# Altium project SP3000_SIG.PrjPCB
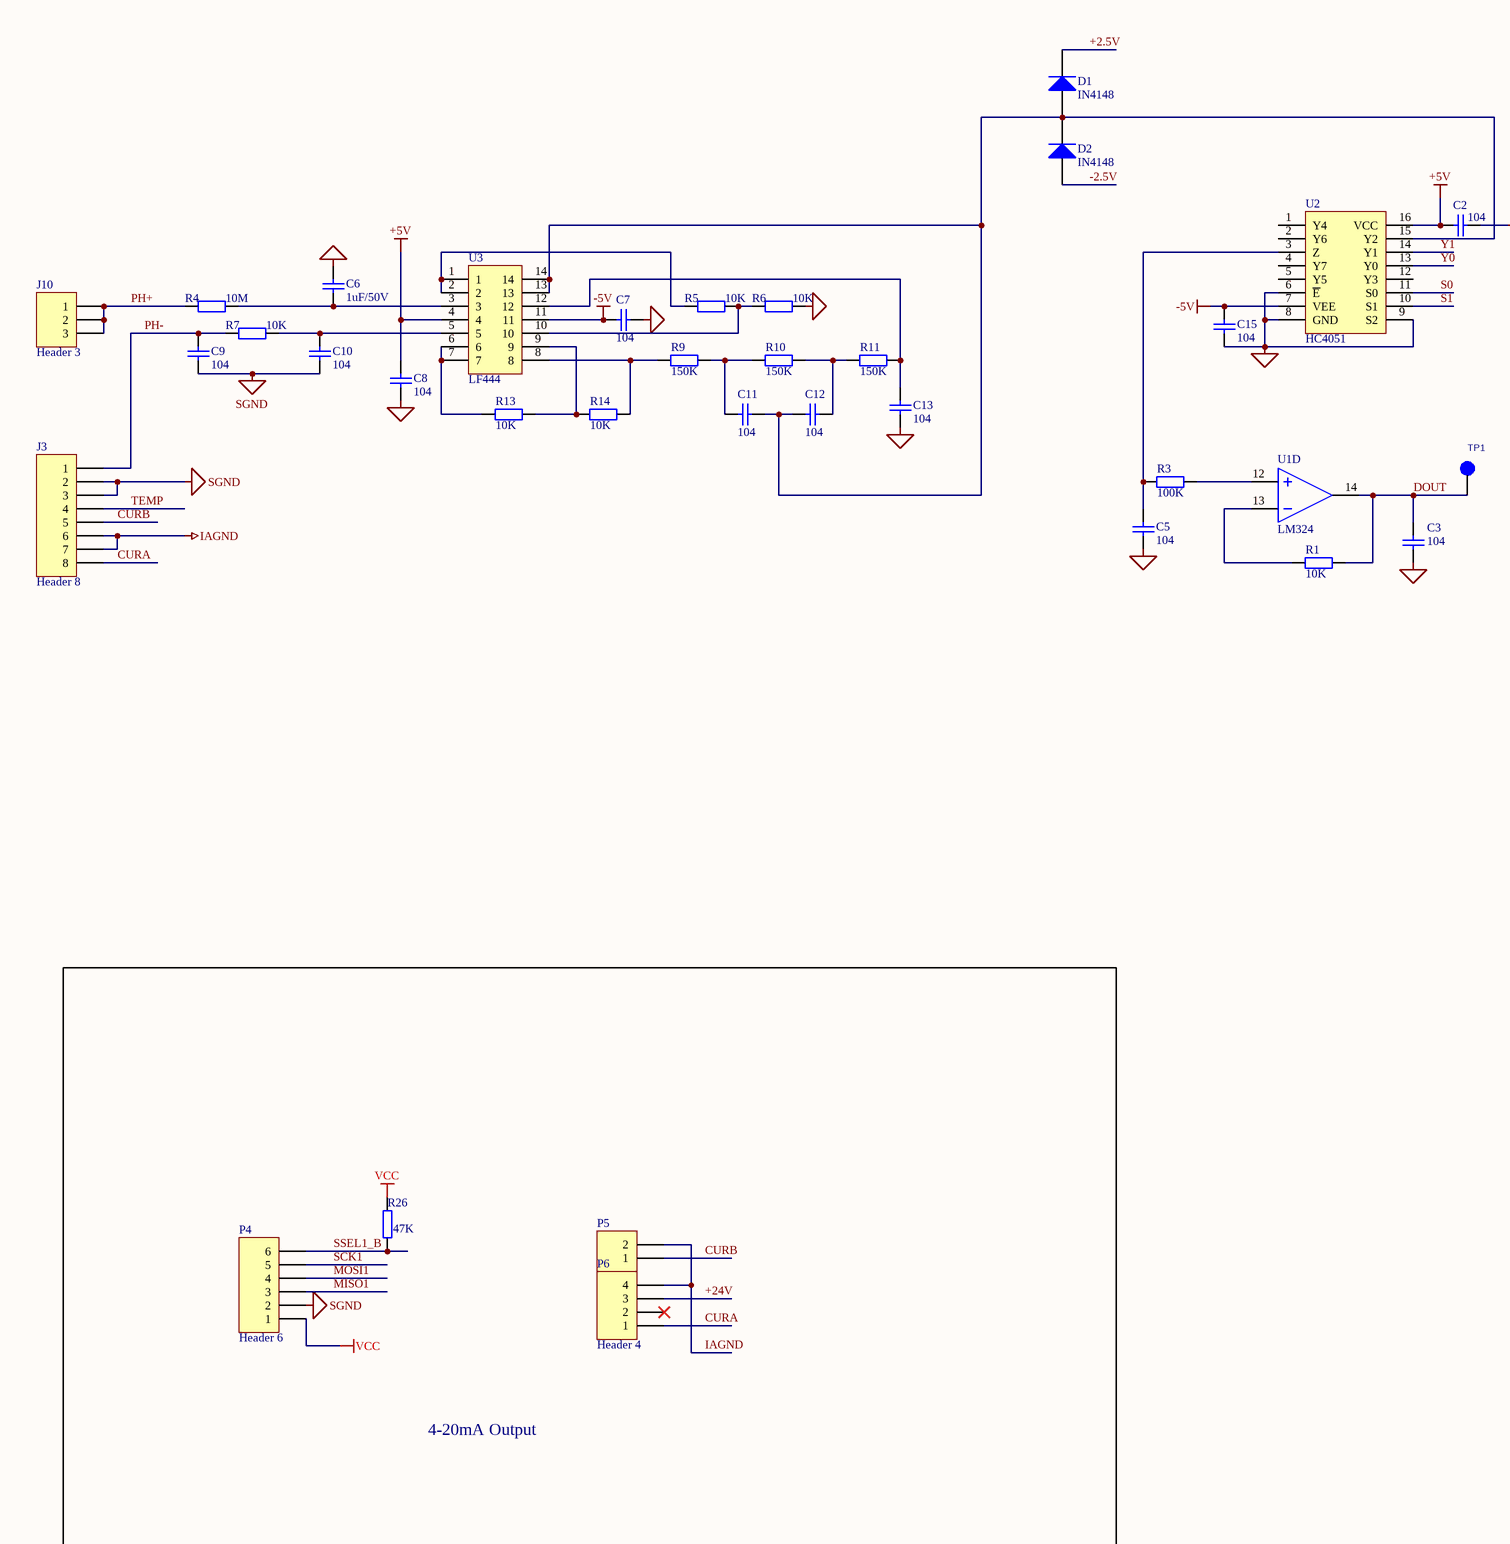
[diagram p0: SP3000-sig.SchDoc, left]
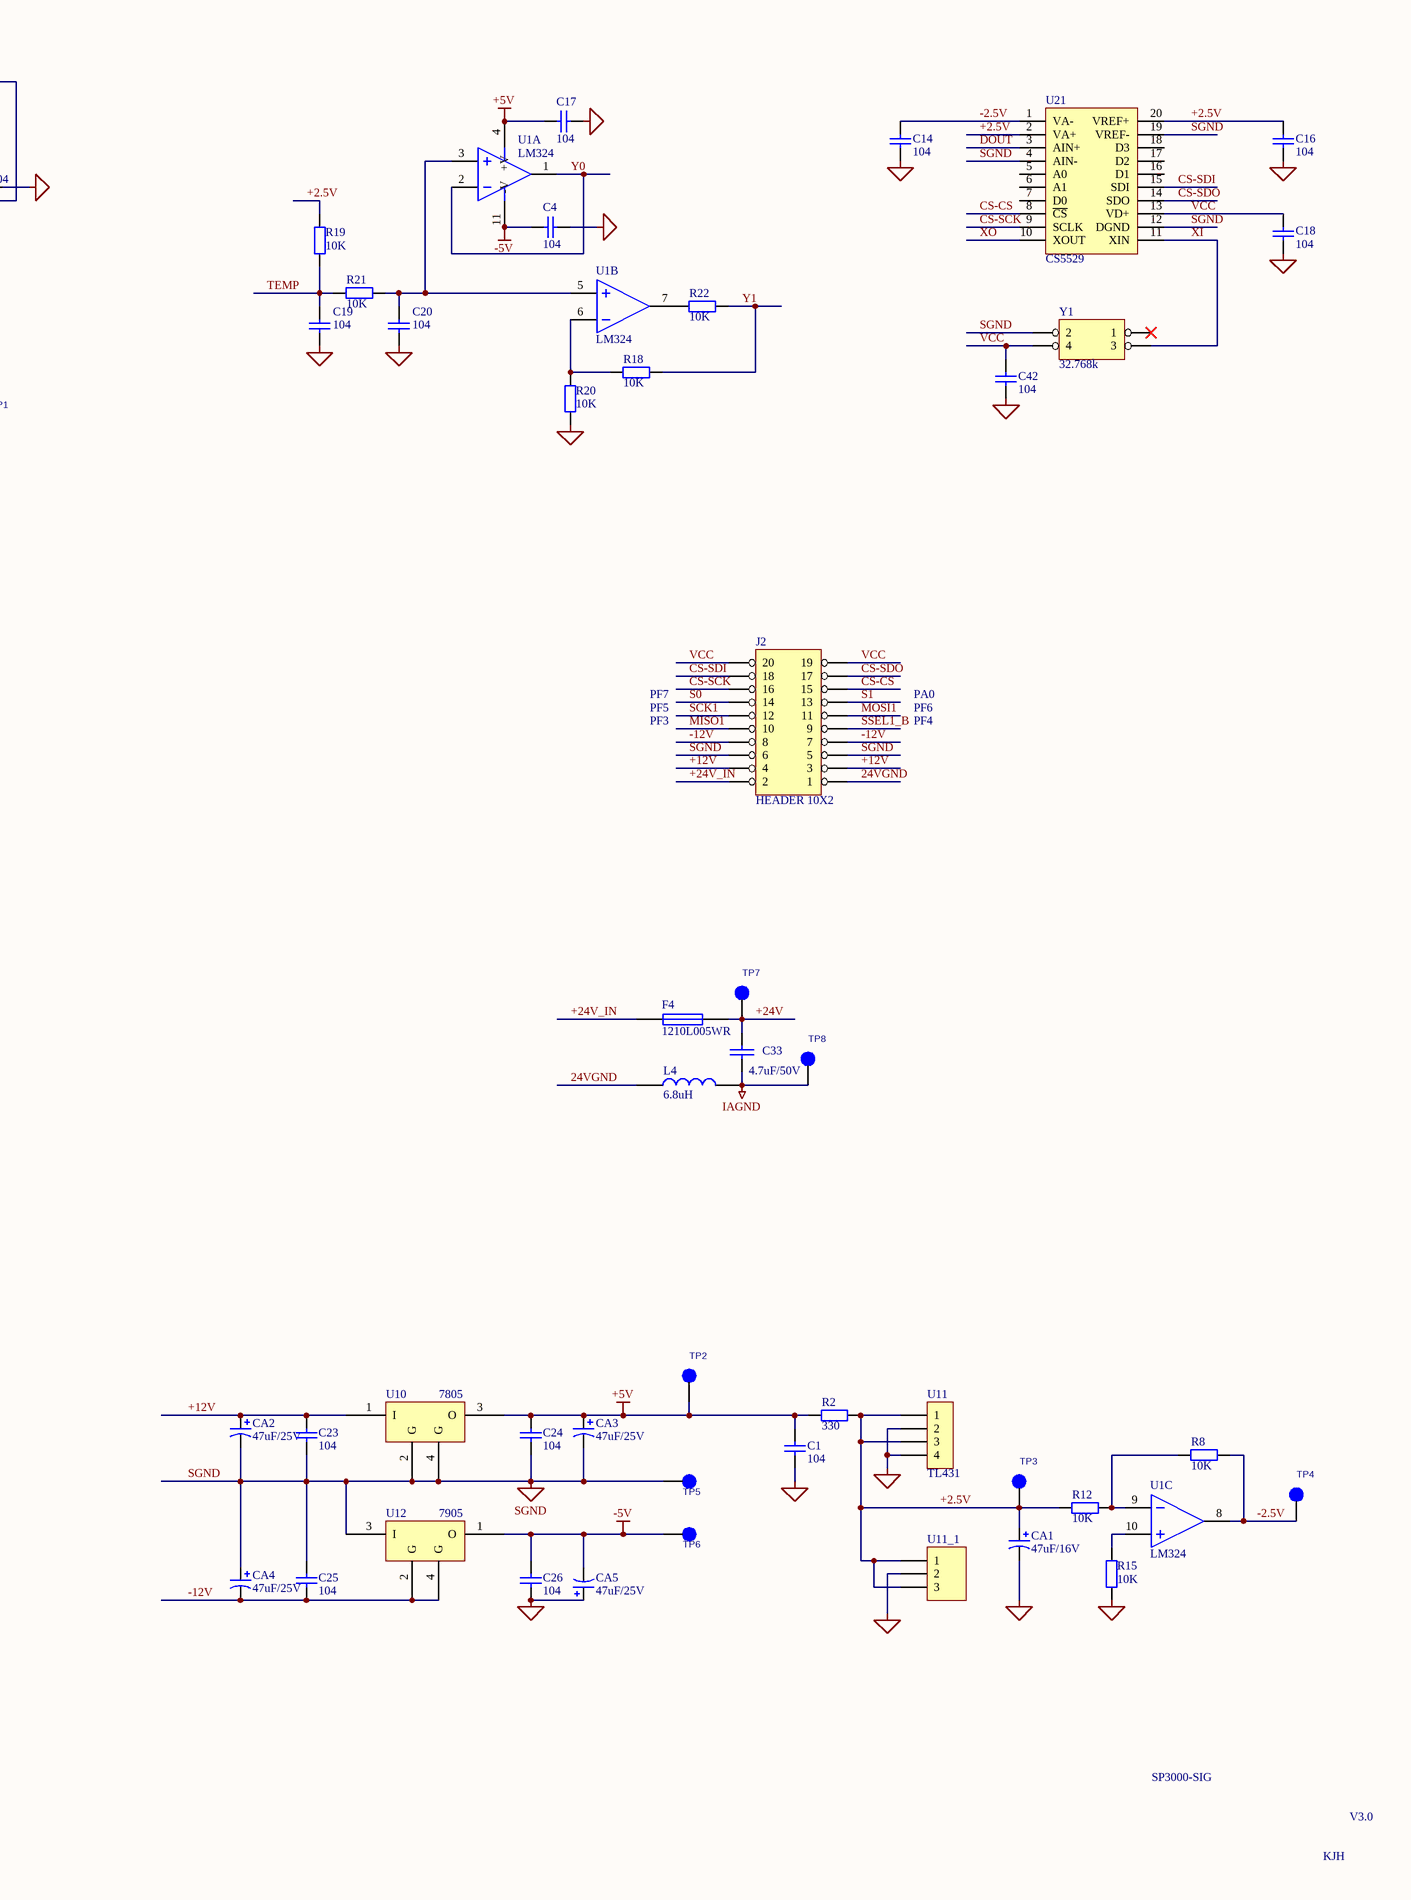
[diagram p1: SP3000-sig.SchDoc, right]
1 sheet, 79 parts. Net scope: global (net labels, ports and power ports of the same name join across sheets).
Board file: SP3000_SIG_V5.2.PcbDoc

## Sheet SP3000-sig.SchDoc
size A2; SheetNumber: 0; SheetTotal: 0

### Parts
C1  104  [0603]
C2  104  [0603]
C3  104  [0603]
C4  104  [0603]
C5  104  [0603]
C6  1uF/50V  [1808C]
C7  104  [0603]
C8  104  [0603]
C9  104  [0603]
C10  104  [0603]
C11  104  [0603]
C12  104  [0603]
C13  104  [0603]
C14  104  [0603]
C15  104  [0603]
C16  104  [0603]
C17  104  [0603]
C18  104  [0603]
C19  104  [0603]
C20  104  [0603]
C23  104  [0603]
C24  104  [0603]
C25  104  [0603]
C26  104  [0603]
C33  4.7uF/50V  [1206]
C42  104  [0603]
CA1  47uF/16V  [1206C]
CA2  47uF/25V  [1206C]
CA3  47uF/25V  [1206C]
CA4  47uF/25V  [1206C]
CA5  47uF/25V  [1206C]
D1  IN4148  [1206]
D2  IN4148  [1206]
F4  1210L005WR  [1206]
J2  HEADER 10X2  [IDC20]
J3  Header 8  [W2318R5MIL]
J10  Header 3  [W2313R5MIL]
L4  6.8uH  [LPS3010]
P4  Header 6  [HDR1X6]
P5  Header 2  [HDR1X2]  (value not drawn)
P6  Header 4  [HDR1X4]
R1  10K  [0603]
R2  330  [0603]
R3  100K  [0603]
R4  10M  [0603]
R5  10K  [0603]
R6  10K  [0603]
R7  10K  [0603]
R8  10K  [0603]
R9  150K  [0603]
R10  150K  [0603]
R11  150K  [0603]
R12  10K  [0603]
R13  10K  [0603]
R14  10K  [0603]
R15  10K  [0603]
R18  10K  [0603]
R19  10K  [0603]
R20  10K  [0603]
R21  10K  [0603]
R22  10K  [0603]
R26  47K  [0603A]
TP1  DOUT  [test point]  (value not drawn)
TP2  P5V  [test point]  (value not drawn)
TP3  P2.5V  [test point]  (value not drawn)
TP4  N2.5V  [test point]  (value not drawn)
TP5  GND  [test point]  (value not drawn)
TP6  N5V  [test point]  (value not drawn)
TP7  P24V  [test point]  (value not drawn)
TP8  AGND  [test point]  (value not drawn)
U1  LM324  [SOP14]  (parts A,B,C,D of 4)
U2  HC4051  [SOP16MAX232]
U3  LF444  [SOP14]
U10  7805  [7805 - DUPLICATE]
U11  TL431  [7805 - DUPLICATE]
U11_1  TL431  [HDR1X3]  (value not drawn)
U12  7905
U21  CS5529  [CS5529]
Y1  32.768k  [CYU-SMD]

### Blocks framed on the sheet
4-20mA Output: P4-P6 R26

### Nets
+5V: C1.1 C2.2 C8.1 C17.1 C24.2 CA3.1 R2.2 TP2.1 U1.4(+V) U2.16(VCC) U3.4 U10.3(O)
-5V: C4.1 C7.1 C15.2 C26.2 CA5.2 TP6.1 U1.11(-V) U2.7(VEE) U3.11 U12.1(O)
IAGND: C33.2 J3.6 J3.7 L4.2 P5.2 P6.4 TP8.1
SGND: C1.2 C2.1 C3.1 C4.2 C5.2 C6.2 C7.2 C8.2 C9.1 C10.1 C13.2 C14.2 C15.1 C16.2 C17.2 C18.2 C19.1 C20.1 C23.1 C24.1 C25.2 C26.1 C42.2 CA1.2 CA2.2 CA3.2 CA4.1 CA5.1 J2.5 J2.6 J3.2 J3.3 P4.2 R6.2 R15.2 R20.2 TP5.1 U2.6(~{E}) U2.8(GND) U2.9(S2) U10.2(G) U10.4(G) U11.2 U11.4 U11_1.2 U12.3(I) U21.4(AIN-) U21.12(DGND) U21.19(VREF-) Y1.2
VCC: C18.1 C42.1 J2.19 J2.20 P4.1 R26.2 U21.13(VD+) Y1.4
24VGND: J2.1 L4.1
+2.5V: C16.1 CA1.1 D1.2(K) R2.1 R12.1 R19.1 TP3.1 U11.1 U11.3 U11_1.1 U11_1.3 U21.2(VA+) U21.20(VREF+)
+12V: C23.2 CA2.1 J2.3 J2.4 U10.1(I)
+24V: C33.1 F4.2 P6.3 TP7.1
+24V_IN: F4.1 J2.2
-2.5V: C14.1 D2.1(A) R8.2 TP4.1 U1.8(OUT) U21.1(VA-)
-12V: C25.1 CA4.2 J2.7 J2.8 U12.2(G) U12.4(G)
CS-CS: J2.15 U21.8(~{CS})
CS-SCK: J2.16 U21.9(SCLK)
CS-SDI: J2.18 U21.15(SDI)
CS-SDO: J2.17 U21.14(SDO)
CURA: J3.8 P6.1
CURB: J3.5 P5.1
DOUT: C3.2 R1.1 TP1.1 U1.14(OUT) U21.3(AIN+)
MISO1: J2.10 P4.3
MOSI1: J2.11 P4.4
PH+: J10.1 J10.2 J10.3 R4.1
PH-: C9.2 J3.1 R7.1
S0: J2.14 U2.11(S0)
S1: J2.13 U2.10(S1)
SCK1: J2.12 P4.5
SSEL1_B: J2.9 P4.6 R26.1
TEMP: C19.2 J3.4 R19.2 R21.2
XI: U21.11(XIN) Y1.3
XO: U21.10(XOUT)
Y0: U1.1(OUT) U1.2(IN-) U2.13(Y0)
Y1: R18.1 R22.1 U2.14(Y1)
NetC5_1: C5.1 R3.2 U2.3(Z)
NetC6_1: C6.1 R4.2 U3.3
NetC10_2: C10.2 R7.2 U3.5
NetC11_1: C11.1 R9.2 R10.1
NetC11_2: C11.2 C12.1 D1.1(A) D2.2(K) U2.15(Y2) U3.13 U3.14
NetC12_2: C12.2 R10.2 R11.1
NetC13_1: C13.1 R11.2 U3.12
NetC20_2: C20.2 R21.1 U1.3(IN+) U1.5(IN+)
NetR1_2: R1.2 U1.13(IN-)
NetR3_1: R3.1 U1.12(IN+)
NetR5_1: R5.1 U3.1 U3.2
NetR5_2: R5.2 R6.1 U3.10
NetR8_1: R8.1 R12.2 U1.9(IN-)
NetR9_1: R9.1 R14.2 U3.8
NetR13_1: R13.1 U3.6 U3.7
NetR13_2: R13.2 R14.1 U3.9
NetR15_1: R15.1 U1.10(IN+)
NetR18_2: R18.2 R20.1 U1.6(IN-)
NetR22_2: R22.2 U1.7(OUT)

Not connected (* = marked no-connect by the designer): P6 2*; U2 1(Y4) 2(Y6) 4(Y7) 5(Y5) 12(Y3); U21 5(A0) 6(A1) 7(D0) 16(D1) 17(D2) 18(D3); Y1 1*

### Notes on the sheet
- PF3
- PF5
- PF7
- PF4
- PF6
- PA0
- SP3000-SIG
- KJH
- V3.0

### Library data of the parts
C1-C5 C7-C20 C23-C26 C42 = Cap: C?
C6 = 无极性电容: C
C33 = CAP: Capacitor
CA1-CA5 = 电解电容: C
D1 D2 = 二极管: DIODE
F4 = FUSE1: Fuse, 50mA
J3 = Header 8: Header, 8-Pin
J10 U11_1 = Header 3: Header, 3-Pin
L4 = INDUCTOR
P4 = Header 6: Header, 6-Pin
P5 = Header 2: Header, 2-Pin
P6 = Header 4: Header, 4-Pin
R1-R15 R18-R22 = Res: R?
R26 = R: 电阻
TP1-TP8 = PAD
U10 = COMPONENT_4
U11 = CON4: Connector
Y1 = HEADER 2X2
